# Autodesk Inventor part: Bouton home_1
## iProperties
Created: 2010-07
Part Number: Bouton home_1
Document SubType Name: Modeling
Designer: eric
Density: 1 g/cm^3
Mass: 0.0401705 g
Surface Area: 0.997731 cm^2
Volume: 0.0401705 cm^3
Author: eric
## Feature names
1. Base1
